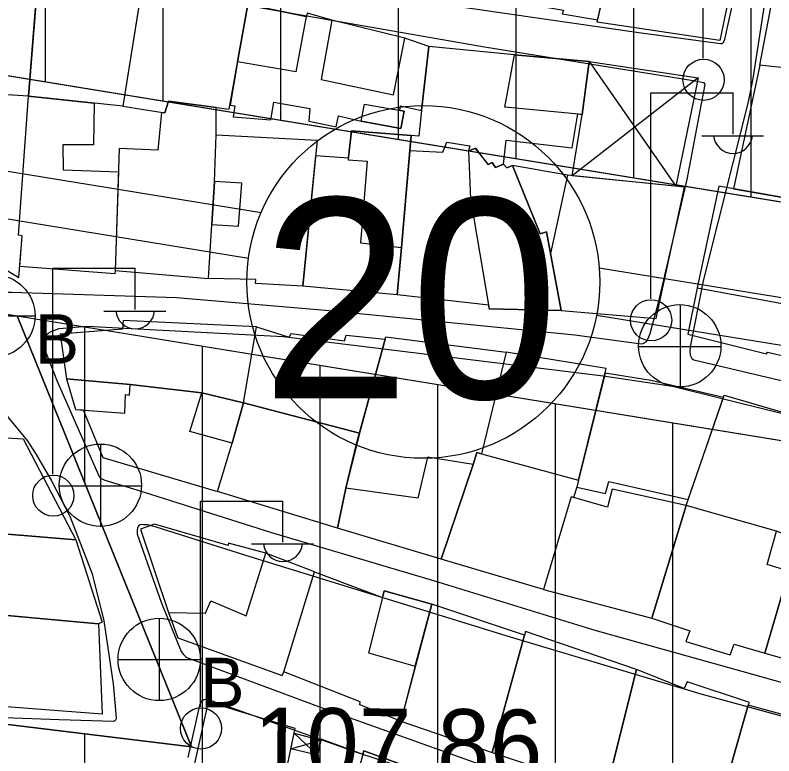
# Model space of a CAD drawing. Extents: x 417997 to 421451, y 4451742 to 4455216.
# Drawn here: x 419340.2 to 419404.7, y 4453167.3 to 4453230.3 of the extents above; entities that cross this region are included whole.
import ezdxf

# ---------------------------------------------------------------- set-up
doc = ezdxf.new("R2010")
doc.units = 0
for name, color, linetype in [('ADA', 7, 'Continuous'), ('ADAKENARI', 7, 'Continuous'), ('B_Mesken', 7, 'Continuous'), ('B_Sundurma', 7, 'Continuous'), ('B_Teras', 7, 'Continuous'), ('Default', 7, 'Continuous'), ('KALDIRIM', 7, 'Continuous'), ('KD_DAIRE', 7, 'Continuous'), ('KD_YGEN', 7, 'Continuous'), ('PL_AYA_PARK_DINLENME', 7, 'Continuous'), ('PL_KON_MEV_350', 7, 'Continuous'), ('S_Elektrik_Diregi', 7, 'Continuous'), ('S_Rogar_Kapagi', 7, 'Continuous'), ('S_Rogar_Kapagi_Buski', 7, 'Continuous'), ('Sinir_Ist_Duvari', 7, 'Continuous'), ('TR_ORTAYOGUNKONUT', 7, 'Continuous'), ('TR_PARKALANI', 7, 'Continuous'), ('Y_Yol_Kotu', 7, 'Continuous'), ('Yol_Sose', 7, 'Continuous')]:
    doc.layers.add(name, color=color, linetype=linetype)

# ---------------------------------------------------------------- blocks, each defined once
blk = doc.blocks.new('POINT_DISPLAY')
at = {"layer": 'Default'}
blk.add_line((0, 0), (0, 0), dxfattribs=at)

msp = doc.modelspace()

# ---------------------------------------------------------------- linework, layer by layer
at = {"layer": 'ADA'}
for p, q in [((419355.2, 4453168.073), (419340.372, 4453204.731)), ((419355.2, 4453168.073), (419340.372, 4453204.731)), ((419323.725, 4453171.911), (419355.2, 4453168.073)), ((419323.725, 4453171.911), (419355.2, 4453168.073))]:
    msp.add_line(p, q, dxfattribs=at)
at = {"layer": 'ADAKENARI'}
for p, q in [((419538.425, 4453192.648), (419256.318, 4453238.725)), ((419538.425, 4453192.648), (419256.318, 4453238.725)), ((419324.529, 4453207.319), (419340.372, 4453204.731)), ((419324.529, 4453207.319), (419340.372, 4453204.731)), ((419340.372, 4453204.731), (419516.46, 4453175.97)), ((419340.372, 4453204.731), (419516.46, 4453175.97))]:
    msp.add_line(p, q, dxfattribs=at)
at = {"layer": 'B_Mesken'}
for points in [[(419380.532, 4453231.817), (419386.799, 4453230.713), (419386.688, 4453230.389), (419389.719, 4453229.887), (419391.678, 4453238.725), (419392.79, 4453238.495), (419393.127, 4453240.219), (419391.941, 4453240.367), (419387.39, 4453241.062), (419387.289, 4453240.447), (419381.723, 4453241.376), (419381.242, 4453238.825)], [(419402.358, 4453239.061), (419400.096, 4453228.133), (419389.675, 4453229.692), (419391.678, 4453238.725), (419392.79, 4453238.495), (419393.127, 4453240.219)], [(419414.161, 4453228.246), (419413.441, 4453224.851), (419410.269, 4453225.312), (419410.221, 4453225.115), (419406.074, 4453225.765), (419403.495, 4453226.048), (419404.677, 4453232.17), (419404.88, 4453232.151), (419405.795, 4453237.026), (419413.759, 4453235.599), (419415.607, 4453235.3), (419415.607, 4453235.3), (419415.472, 4453234.642)], [(419332.76, 4453235.208), (419342.211, 4453234.407), (419341.317, 4453223.409), (419331.9, 4453223.995)], [(419341.317, 4453223.409), (419342.25, 4453234.892), (419351.183, 4453234.11), (419349.356, 4453222.556)], [(419349.356, 4453222.556), (419352.927, 4453221.973), (419353.233, 4453222.97), (419358.401, 4453222.287), (419360.275, 4453232.92), (419352.836, 4453234.117), (419352.491, 4453231.741), (419350.841, 4453231.948)], [(419358.463, 4453222.636), (419358.869, 4453222.577), (419358.739, 4453221.644), (419361.938, 4453221.376), (419362.181, 4453222.903), (419365.254, 4453222.339), (419365.164, 4453221.271), (419367.479, 4453220.796), (419367.69, 4453221.741), (419369.617, 4453221.273), (419372.989, 4453220.665), (419373.259, 4453222.123), (419372.903, 4453222.186), (419372.96, 4453222.578), (419374.733, 4453222.178), (419375.374, 4453227.639), (419373.328, 4453228.321), (419367.106, 4453229.855), (419365.063, 4453230.453), (419364.939, 4453230.184), (419359.973, 4453231.203), (419359.112, 4453226.323)], [(419387.56, 4453219.004), (419388.02, 4453221.892), (419388.414, 4453221.856), (419389.009, 4453226.34), (419382.648, 4453226.913), (419375.374, 4453227.639), (419374.733, 4453222.178), (419374.526, 4453219.988), (419373.874, 4453220.054), (419373.763, 4453218.786), (419376.556, 4453218.645), (419376.888, 4453219.48), (419378.839, 4453219.187), (419378.745, 4453218.751), (419379.312, 4453218.965), (419380.416, 4453217.594), (419380.743, 4453217.753), (419381.038, 4453217.343), (419381.718, 4453217.633), (419381.952, 4453219.66)], [(419403.495, 4453226.048), (419401.253, 4453215.525), (419407.733, 4453214.381), (419410.827, 4453213.692), (419411.927, 4453213.325), (419412.578, 4453213.29), (419413.008, 4453216.103), (419413.12, 4453216.4), (419411.79, 4453216.578), (419413.441, 4453224.851), (419410.269, 4453225.312), (419410.221, 4453225.115), (419406.074, 4453225.765)], [(419326.291, 4453224.344), (419326.151, 4453220.559), (419336.579, 4453210.348), (419340.515, 4453207.975), (419340.787, 4453211.515), (419340.49, 4453211.572), (419341.317, 4453223.409)], [(419346.904, 4453222.816), (419346.848, 4453219.263), (419344.24, 4453219.267), (419344.277, 4453217.151), (419348.985, 4453216.976), (419348.697, 4453208.585), (419348.667, 4453208.287), (419340.588, 4453208.922), (419340.787, 4453211.515), (419340.49, 4453211.572), (419341.317, 4453223.409)], [(419357.281, 4453220.116), (419357.275, 4453222.435), (419353.233, 4453222.97), (419352.927, 4453221.973), (419352.637, 4453222.02), (419352.339, 4453218.823), (419349.052, 4453218.943), (419348.697, 4453208.585), (419356.63, 4453207.885), (419356.924, 4453212.475), (419357.139, 4453216.144)], [(419356.63, 4453207.885), (419356.924, 4453212.475), (419357.139, 4453216.144), (419357.281, 4453220.116), (419365.879, 4453219.671), (419364.641, 4453207.243), (419360.64, 4453207.47), (419360.666, 4453207.818)], [(419365.748, 4453218.354), (419368.536, 4453218.167), (419368.78, 4453220.466), (419373.874, 4453220.054), (419373.038, 4453210.537), (419372.68, 4453206.506), (419364.641, 4453207.243)], [(419373.763, 4453218.786), (419376.556, 4453218.645), (419376.888, 4453219.48), (419378.839, 4453219.187), (419378.745, 4453218.751), (419379.312, 4453218.965), (419380.416, 4453217.594), (419380.743, 4453217.753), (419381.038, 4453217.343), (419381.718, 4453217.633), (419381.987, 4453217.305), (419382.476, 4453217.516), (419384.843, 4453211.696), (419385.359, 4453211.879), (419386.606, 4453205.179), (419380.506, 4453205.306), (419380.452, 4453205.626), (419372.68, 4453206.506), (419373.038, 4453210.537)], [(419387.141, 4453216.68), (419385.704, 4453210.025), (419386.606, 4453205.179), (419394.685, 4453204.488), (419397.109, 4453215.67)], [(419408.063, 4453200.727), (419410.203, 4453210.369), (419408.741, 4453210.792), (419408.972, 4453212.415), (419410.543, 4453212.206), (419410.827, 4453213.692), (419407.733, 4453214.381), (419400.012, 4453215.744), (419398.179, 4453207.101), (419397.387, 4453203.156), (419404.074, 4453201.48), (419404.157, 4453201.641)], [(419360.71, 4453203.774), (419349.368, 4453204.316), (419349.308, 4453203.586), (419344.012, 4453203.162), (419344.548, 4453199.358), (419349.966, 4453198.881), (419356.067, 4453198.184), (419359.599, 4453197.319)], [(419367.586, 4453186.678), (419368.313, 4453190.061), (419369.239, 4453193.947), (419369.459, 4453194.748), (419371.649, 4453202.746), (419371.699, 4453202.929), (419381.942, 4453201.641), (419379.837, 4453192.979), (419379.458, 4453193.092), (419379.125, 4453192.094), (419376.401, 4453184.035)], [(419381.942, 4453201.641), (419379.837, 4453192.979), (419388.092, 4453190.74), (419390.448, 4453200.238)], [(419358.65, 4453193.894), (419359.599, 4453197.319), (419356.067, 4453198.184), (419349.966, 4453198.881), (419344.548, 4453199.358), (419345.314, 4453196.77), (419345.977, 4453196.721), (419347.645, 4453192.689), (419357.395, 4453189.792)], [(419400.401, 4453197.77), (419394.229, 4453199.226), (419390.35, 4453199.843), (419388.092, 4453190.74), (419387.952, 4453190.146), (419390.388, 4453189.602), (419390.668, 4453190.627), (419397.423, 4453189.115)], [(419404.915, 4453186.399), (419397.24, 4453188.581), (419400.475, 4453197.986), (419410.265, 4453195.116), (419408.896, 4453191.191), (419407.359, 4453186.784), (419406.956, 4453185.611)], [(419367.586, 4453186.678), (419357.395, 4453189.792), (419358.65, 4453193.894), (419359.599, 4453197.319), (419369.459, 4453194.748), (419368.313, 4453190.061)], [(419337.083, 4453194.478), (419340.875, 4453194.27), (419345.364, 4453185.675), (419336.129, 4453186.437), (419333.873, 4453186.575), (419334.203, 4453194.58)], [(419385.101, 4453181.443), (419376.401, 4453184.035), (419379.125, 4453192.094), (419379.458, 4453193.092), (419379.837, 4453192.979), (419388.092, 4453190.74), (419387.952, 4453190.146), (419387.673, 4453189.265), (419387.469, 4453189.323)], [(419385.101, 4453181.443), (419394.335, 4453179.015), (419397.24, 4453188.581), (419390.947, 4453189.984), (419390.554, 4453188.447), (419387.469, 4453189.323)], [(419397.24, 4453188.581), (419394.335, 4453179.015), (419397.561, 4453177.945), (419397.2, 4453177.027), (419400.97, 4453175.896), (419401.331, 4453176.814), (419403.934, 4453176.05), (419405.975, 4453183.023), (419404.131, 4453183.588), (419404.915, 4453186.399)], [(419365.641, 4453182.948), (419361.502, 4453184.543), (419358.334, 4453185.395), (419358.305, 4453185.178), (419352.05, 4453187.016), (419350.853, 4453186.57), (419353.238, 4453179.498), (419354.035, 4453177.349), (419362.883, 4453174.125), (419363.048, 4453174.448)], [(419336.069, 4453179.544), (419335.639, 4453179.57), (419336.129, 4453186.437), (419345.364, 4453185.675), (419347.607, 4453178.673), (419347.281, 4453178.532)], [(419416.352, 4453182.001), (419406.706, 4453184.937), (419405.975, 4453183.023), (419403.934, 4453176.05), (419413.71, 4453173.299)], [(419372.975, 4453170.263), (419369.485, 4453171.633), (419369.541, 4453171.904), (419363.048, 4453174.448), (419365.641, 4453182.948), (419371.425, 4453180.757), (419371.572, 4453181.332), (419375.606, 4453180.199), (419374.215, 4453174.945)], [(419383.51, 4453177.556), (419375.606, 4453180.199), (419372.975, 4453170.263), (419380.742, 4453167.596)], [(419336.069, 4453179.544), (419347.28, 4453178.542), (419347.597, 4453170.853), (419335.722, 4453171.768)], [(419383.596, 4453177.867), (419380.742, 4453167.596), (419390.442, 4453164.359), (419393.025, 4453174.66)], [(419402.508, 4453171.624), (419402.618, 4453171.839), (419397.323, 4453173.607), (419397.075, 4453173.043), (419393.025, 4453174.66), (419390.442, 4453164.359), (419390.304, 4453164.009), (419399.525, 4453161.226), (419399.608, 4453161.468)], [(419362.158, 4453160.847), (419363.99, 4453169.637), (419356.604, 4453171.908), (419354.556, 4453162.679), (419355.441, 4453162.366), (419361.436, 4453160.952)], [(419402.508, 4453171.624), (419399.608, 4453161.468), (419409.242, 4453158.327), (419412.165, 4453168.478), (419412.277, 4453168.936)], [(419366.191, 4453168.739), (419369.759, 4453167.453), (419369.832, 4453167.719), (419376.149, 4453165.448), (419374.362, 4453157.504), (419367.449, 4453159.03), (419364.815, 4453159.543), (419364.997, 4453160.436), (419365.535, 4453163.045), (419364.985, 4453163.201)]]:
    msp.add_lwpolyline(points, close=True, dxfattribs=at)
at = {"layer": 'B_Sundurma'}
for p, q in [((419389.009, 4453226.34), (419396.368, 4453215.745)), ((419398.269, 4453224.955), (419387.553, 4453216.638)), ((419363.907, 4453169.238), (419365.894, 4453167.376)), ((419363.629, 4453167.905), (419366.17, 4453168.642))]:
    msp.add_line(p, q, dxfattribs=at)
for points in [[(419389.009, 4453226.34), (419398.269, 4453224.955), (419396.368, 4453215.745), (419387.553, 4453216.638), (419388.414, 4453221.856)], [(419363.629, 4453167.905), (419363.907, 4453169.238), (419366.17, 4453168.642), (419365.894, 4453167.376)]]:
    msp.add_lwpolyline(points, close=True, dxfattribs=at)
at = {"layer": 'B_Teras'}
for points in [[(419359.973, 4453231.203), (419364.939, 4453230.184), (419364.061, 4453225.472), (419359.112, 4453226.323)], [(419367.106, 4453229.855), (419366.225, 4453224.805), (419372.368, 4453223.529), (419373.328, 4453228.321)], [(419381.837, 4453222.453), (419382.648, 4453226.913), (419389.009, 4453226.34), (419388.414, 4453221.856)], [(419372.989, 4453220.665), (419369.617, 4453221.273), (419369.9, 4453222.718), (419373.259, 4453222.123)], [(419368.78, 4453220.466), (419368.516, 4453217.98), (419370.115, 4453217.879), (419369.543, 4453210.931), (419373.038, 4453210.537), (419373.874, 4453220.054)], [(419379.37, 4453218.987), (419378.745, 4453218.751), (419378.901, 4453214.662), (419380.506, 4453205.306), (419386.606, 4453205.179), (419385.359, 4453211.879), (419384.843, 4453211.696), (419382.476, 4453217.516), (419381.987, 4453217.305), (419381.718, 4453217.633), (419381.038, 4453217.343), (419380.743, 4453217.753), (419380.416, 4453217.594)], [(419356.924, 4453212.475), (419359.174, 4453212.34), (419359.47, 4453216.003), (419357.139, 4453216.144)], [(419400.012, 4453215.744), (419398.179, 4453207.101), (419406.034, 4453205.654), (419407.733, 4453214.381)], [(419369.459, 4453194.748), (419359.599, 4453197.319), (419360.71, 4453203.774), (419363.496, 4453202.901), (419363.662, 4453203.224), (419368.186, 4453202.6), (419368.326, 4453203.085), (419371.649, 4453202.746)], [(419369.239, 4453193.947), (419371.699, 4453202.929), (419381.942, 4453201.641), (419379.837, 4453192.979), (419379.458, 4453193.092), (419379.125, 4453192.094), (419375.251, 4453192.71), (419374.436, 4453189.228), (419368.313, 4453190.061)], [(419344.548, 4453199.358), (419345.314, 4453196.77), (419349.515, 4453196.458), (419349.584, 4453198.026), (419349.92, 4453197.975), (419349.966, 4453198.881)], [(419356.067, 4453198.184), (419359.599, 4453197.319), (419358.65, 4453193.894), (419355.06, 4453194.9)], [(419352.05, 4453187.016), (419350.853, 4453186.57), (419353.238, 4453179.498), (419356.385, 4453179.433), (419356.828, 4453180.483), (419359.83, 4453179.201), (419361.502, 4453184.543), (419358.334, 4453185.395), (419358.305, 4453185.178)], [(419370.225, 4453176.056), (419374.215, 4453174.945), (419375.606, 4453180.199), (419371.572, 4453181.332)], [(419374.362, 4453157.504), (419376.149, 4453165.448), (419369.832, 4453167.719), (419367.449, 4453159.03)]]:
    msp.add_lwpolyline(points, close=True, dxfattribs=at)
at = {"layer": 'KALDIRIM'}
for p, q in [((419240.438, 4453233.213), (419361.105, 4453213.504)), ((419240.438, 4453233.213), (419361.105, 4453213.504)), ((419245.714, 4453228.298), (419360.033, 4453209.626)), ((419245.714, 4453228.298), (419360.033, 4453209.626)), ((419389.848, 4453208.809), (419533.584, 4453185.332)), ((419389.848, 4453208.809), (419533.584, 4453185.332)), ((419389.63, 4453204.792), (419519.061, 4453183.651)), ((419389.63, 4453204.792), (419519.061, 4453183.651))]:
    msp.add_line(p, q, dxfattribs=at)
at = {"layer": 'KD_DAIRE'}
msp.add_circle((419374.896, 4453207.606), 15, dxfattribs=at)
msp.add_circle((419374.896, 4453207.606), 15, dxfattribs=at)
at = {"layer": 'PL_AYA_PARK_DINLENME'}
msp.add_lwpolyline([(419323.725, 4453171.911), (419324.529, 4453207.319), (419340.372, 4453204.731), (419355.2, 4453168.073)], close=True, dxfattribs=at)
msp.add_lwpolyline([(419323.725, 4453171.911), (419324.529, 4453207.319), (419340.372, 4453204.731), (419355.2, 4453168.073)], close=True, dxfattribs=at)
at = {"layer": 'PL_KON_MEV_350'}
for points in [[(419660.82, 4453311.511), (419569.02, 4453203.864), (419566.405, 4453201.13), (419563.496, 4453198.712), (419560.331, 4453196.641), (419556.951, 4453194.943), (419553.4, 4453193.641), (419549.723, 4453192.751), (419545.969, 4453192.286), (419542.186, 4453192.252), (419538.425, 4453192.648), (419256.318, 4453238.725)], [(419238.503, 4453221.37), (419324.529, 4453207.319), (419323.725, 4453171.911), (419355.2, 4453168.073), (419340.372, 4453204.731), (419516.46, 4453175.97)]]:
    msp.add_lwpolyline(points, dxfattribs=at)
at = {"layer": 'S_Elektrik_Diregi'}
for p, q in [((419398.683, 4453226.632), (419398.683, 4453244.132)), ((419394.228, 4453206.179), (419394.228, 4453223.679)), ((419394.228, 4453223.679), (419401.228, 4453223.679)), ((419401.228, 4453220.179), (419401.228, 4453223.679)), ((419398.568, 4453220.039), (419403.818, 4453220.039)), ((419343.403, 4453191.271), (419343.403, 4453208.771)), ((419343.403, 4453208.771), (419350.403, 4453208.771)), ((419350.403, 4453205.271), (419350.403, 4453208.771)), ((419347.743, 4453205.131), (419352.993, 4453205.131)), ((419355.959, 4453171.47), (419355.959, 4453188.97)), ((419355.959, 4453188.97), (419362.959, 4453188.97)), ((419362.959, 4453185.47), (419362.959, 4453188.97)), ((419360.299, 4453185.33), (419365.549, 4453185.33))]:
    msp.add_line(p, q, dxfattribs=at)
for centre in [(419398.719, 4453224.797), (419394.264, 4453204.344), (419343.439, 4453189.436), (419355.995, 4453169.634)]:
    msp.add_circle(centre, 1.75, dxfattribs=at)
for centre in [(419401.229, 4453220.192), (419350.404, 4453205.284), (419362.96, 4453185.483)]:
    msp.add_arc(centre, 1.658, 184.83843, 355.14641, dxfattribs=at)
at = {"layer": 'S_Rogar_Kapagi'}
for p, q in [((419396.747, 4453198.644), (419396.747, 4453205.644)), ((419393.177, 4453202.109), (419400.177, 4453202.109)), ((419347.494, 4453186.789), (419347.494, 4453193.789)), ((419343.924, 4453190.254), (419350.924, 4453190.254))]:
    msp.add_line(p, q, dxfattribs=at)
for centre in [(419396.693, 4453202.172), (419347.441, 4453190.318)]:
    msp.add_circle(centre, 3.5, dxfattribs=at)
at = {"layer": 'S_Rogar_Kapagi_Buski'}
for p, q in [((419334.884, 4453204.724), (419341.884, 4453204.724)), ((419352.444, 4453179.004), (419352.444, 4453172.004)), ((419348.944, 4453175.504), (419355.944, 4453175.504))]:
    msp.add_line(p, q, dxfattribs=at)
for centre in [(419338.384, 4453204.724), (419352.444, 4453175.504)]:
    msp.add_circle(centre, 3.5, dxfattribs=at)
at = {"layer": 'Sinir_Ist_Duvari'}
msp.add_lwpolyline([(419387.141, 4453216.68), (419382.476, 4453217.516)], dxfattribs=at)
at = {"layer": 'TR_ORTAYOGUNKONUT'}
for p, q in [((419352.78, 4453222.97), (419352.78, 4453416.04)), ((419352.78, 4453222.97), (419352.78, 4453416.04)), ((419362.78, 4453221.336), (419362.78, 4453413.87)), ((419362.78, 4453221.336), (419362.78, 4453413.87)), ((419372.78, 4453219.703), (419372.78, 4453411.699)), ((419372.78, 4453219.703), (419372.78, 4453411.699)), ((419382.78, 4453218.07), (419382.78, 4453409.681)), ((419382.78, 4453218.07), (419382.78, 4453409.681)), ((419392.78, 4453216.436), (419392.78, 4453408.655)), ((419392.78, 4453216.436), (419392.78, 4453408.655)), ((419402.78, 4453214.803), (419402.78, 4453408.816)), ((419402.78, 4453214.803), (419402.78, 4453408.816)), ((419342.78, 4453224.603), (419342.78, 4453303.837)), ((419342.78, 4453224.603), (419342.78, 4453303.837)), ((419346.12, 4453190.521), (419346.12, 4453203.792)), ((419346.12, 4453190.521), (419346.12, 4453203.792)), ((419356.12, 4453143.795), (419356.12, 4453202.159)), ((419356.12, 4453143.795), (419356.12, 4453202.159)), ((419366.12, 4453146.454), (419366.12, 4453200.526)), ((419366.12, 4453146.454), (419366.12, 4453200.526)), ((419376.12, 4453144.918), (419376.12, 4453198.892)), ((419376.12, 4453144.918), (419376.12, 4453198.892)), ((419386.12, 4453138.062), (419386.12, 4453197.259)), ((419386.12, 4453138.062), (419386.12, 4453197.259)), ((419396.12, 4453052.846), (419396.12, 4453195.626)), ((419396.12, 4453052.846), (419396.12, 4453195.626)), ((419346.12, 4453134.601), (419346.12, 4453169.18)), ((419346.12, 4453134.601), (419346.12, 4453169.18))]:
    msp.add_line(p, q, dxfattribs=at)
at = {"layer": 'Yol_Sose'}
for points in [[(419404.832, 4453237.799), (419403.778, 4453230.579), (419402.904, 4453224.892), (419402.513, 4453222.922)], [(419397.295, 4453216.321), (419394.821, 4453205.727), (419394.149, 4453203.183), (419393.981, 4453202.774), (419393.838, 4453202.505), (419393.682, 4453202.384), (419393.551, 4453202.333), (419393.408, 4453202.316), (419387.768, 4453203.077), (419375.791, 4453204.264), (419366.573, 4453205.186), (419353.921, 4453206.255), (419339.899, 4453206.706), (419336.559, 4453206.695), (419336.162, 4453206.814), (419335.712, 4453207.133), (419330.761, 4453211.877), (419325.888, 4453217.03), (419324.301, 4453218.781), (419323.896, 4453219.165), (419321.583, 4453222.108), (419317.953, 4453227.72), (419315.044, 4453233.445)], [(419352.934, 4453232.386), (419364.993, 4453230.243), (419380.103, 4453227.606), (419397.847, 4453224.745), (419398.722, 4453224.556), (419398.822, 4453224.426), (419398.825, 4453224.403)], [(419401.331, 4453231.997), (419400.478, 4453228.094), (419400.368, 4453227.91), (419400.336, 4453227.903), (419400.264, 4453227.858), (419400.158, 4453227.847), (419393.416, 4453228.762), (419376.12, 4453231.263)], [(419398.825, 4453224.403), (419397.295, 4453216.321)], [(419402.513, 4453222.922), (419398.698, 4453207.697), (419397.574, 4453202.091), (419397.546, 4453201.718), (419397.571, 4453201.379), (419397.731, 4453201.089), (419397.883, 4453200.987), (419412.4, 4453197.563), (419421.701, 4453195.625), (419422.021, 4453195.631), (419422.078, 4453195.668), (419422.143, 4453195.746), (419422.921, 4453203.468)], [(419343.769, 4453199.201), (419342.703, 4453201.933), (419342.606, 4453202.269), (419342.582, 4453202.495), (419342.624, 4453202.752), (419342.706, 4453202.925), (419342.848, 4453203.121), (419343.053, 4453203.289), (419343.266, 4453203.394), (419343.928, 4453203.64), (419346.289, 4453203.844), (419362.967, 4453202.954), (419390.183, 4453199.613), (419396.09, 4453198.75), (419409.076, 4453195.496), (419420.506, 4453192.979), (419431.316, 4453191.053), (419445.611, 4453188.704), (419448.825, 4453188.42), (419451.49, 4453188.36), (419455.367, 4453187.984), (419460.844, 4453187.224), (419471.34, 4453185.319), (419483.429, 4453183.292)], [(419337.478, 4453198.616), (419341.214, 4453194.123), (419341.989, 4453192.928), (419343.3, 4453190.698), (419344.831, 4453187.7), (419346.739, 4453182.789), (419347.735, 4453178.775), (419348.529, 4453173.428), (419348.701, 4453171.524), (419348.773, 4453170.489), (419348.745, 4453170.362), (419348.67, 4453170.28), (419348.56, 4453170.219), (419343.935, 4453170.367), (419333.038, 4453170.755)], [(419347.333, 4453191.083), (419343.769, 4453199.201)], [(419475.768, 4453152.445), (419462.576, 4453156.596), (419443.875, 4453162.943), (419439.701, 4453164.272), (419433.93, 4453165.911), (419418.322, 4453169.899), (419401.995, 4453174.465), (419389.511, 4453177.959), (419375.877, 4453182.163), (419362.017, 4453186.282), (419350.559, 4453189.888), (419347.848, 4453190.719), (419347.545, 4453190.872), (419347.333, 4453191.083)], [(419398.513, 4453172.559), (419382.317, 4453177.383), (419359.709, 4453184.374), (419352.1, 4453186.775), (419351.453, 4453186.952), (419351.103, 4453186.957), (419350.912, 4453186.97), (419350.824, 4453186.945), (419350.685, 4453186.858), (419350.584, 4453186.669), (419350.555, 4453186.516), (419350.581, 4453186.149), (419352.597, 4453180.366), (419354.307, 4453176.187), (419354.501, 4453175.918), (419354.695, 4453175.727), (419354.716, 4453175.703), (419366.306, 4453171.382), (419379.133, 4453166.803), (419379.547, 4453166.615), (419379.818, 4453166.346), (419379.95, 4453166.049), (419378.362, 4453157.982)], [(419354.894, 4453167.165), (419355.902, 4453171.628), (419355.972, 4453171.828), (419356.115, 4453172.019), (419356.235, 4453172.102), (419356.506, 4453172.139), (419356.556, 4453172.135), (419369.293, 4453167.601), (419375.789, 4453165.464)], [(419460.308, 4453153.946), (419449.642, 4453157.784), (419440.894, 4453160.532), (419425.632, 4453165.186), (419414.047, 4453168.311), (419398.513, 4453172.559)]]:
    msp.add_lwpolyline(points, dxfattribs=at)

# ---------------------------------------------------------------- block references
at = {"layer": 'TR_PARKALANI', "xscale": 0.1, "yscale": 0.10000000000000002}
for p in [(419346.608, 4453182.262), (419346.608, 4453182.262), (419349.378, 4453173.752), (419349.378, 4453173.752)]:
    msp.add_blockref('POINT_DISPLAY', p, dxfattribs=at)

# ---------------------------------------------------------------- texts
at = {"layer": 'KD_YGEN'}
msp.add_text('20', height=17, dxfattribs=at).set_placement((419361.132, 4453197.71))
msp.add_text('20', height=17, dxfattribs=at).set_placement((419361.132, 4453197.71))
at = {"layer": 'S_Rogar_Kapagi_Buski'}
for p in [(419341.884, 4453200.66), (419355.944, 4453171.44)]:
    msp.add_text('B', height=4.2, dxfattribs=at).set_placement(p)
at = {"layer": 'Y_Yol_Kotu'}
msp.add_text('107.86 ', height=6, rotation=359.53575, dxfattribs=at).set_placement((419360.449, 4453165.418))

doc.saveas('drawing.dxf')
